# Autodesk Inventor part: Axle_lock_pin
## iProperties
Shininess: 69.0
Length Units: 11269
Angle Units: 11279
Time Units: 11290
Mass Units: 11283
Length Display Precision: 3
Angle Display Precision: 2
Created: 2001-04
Part Number: Axle_lock_pin
Material: Standard
Document SubType Name: Modellieren
Designer: dl
Density: 0.0
Volumn: 0.0
Area: 0.0
PropertySet Name: Model Information
Control State: 0
Master: False
Checked Out: False
Author: dl
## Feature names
1. Revolution1
2. Chamfer1
3. Extrusion1
4. Extrusion2
5. Fillet1
6. Circular Pattern1
7. Fillet2
8. Chamfer2
